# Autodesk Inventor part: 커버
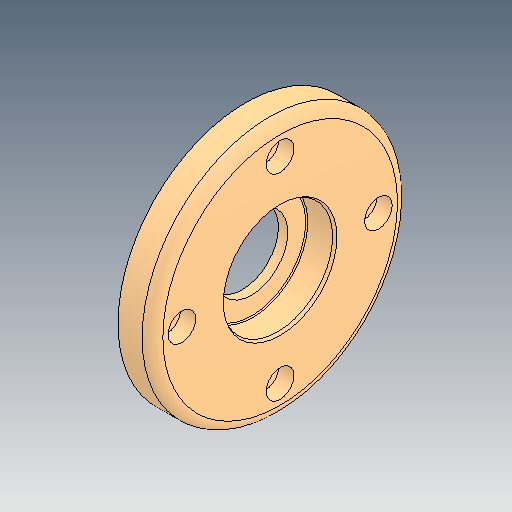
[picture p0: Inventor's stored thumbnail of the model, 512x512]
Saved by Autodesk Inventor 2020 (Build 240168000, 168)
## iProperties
Created: 2024-11
Part Number: 커버
Material: 알루미늄 6061
Document SubType Name: Modeling
Designer: shin
Density: 2.7 g/cm^3
Appearance: 기본값
Author: jhkim
Sending System: Autodesk Inventor 2025
Preprocessor: ST-DEVELOPER v20
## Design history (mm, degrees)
feature "솔리드1"
node "솔리드2"
